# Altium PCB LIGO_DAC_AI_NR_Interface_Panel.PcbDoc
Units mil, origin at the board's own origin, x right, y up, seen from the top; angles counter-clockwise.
Board outline 6300 x 11000 mil, 4 copper layers (Top Layer, Mid-Layer 1, Mid-Layer 2, Bottom Layer), stack 61.8 mil thick; 0 components, 0 nets, 82 pads, 0 vias.
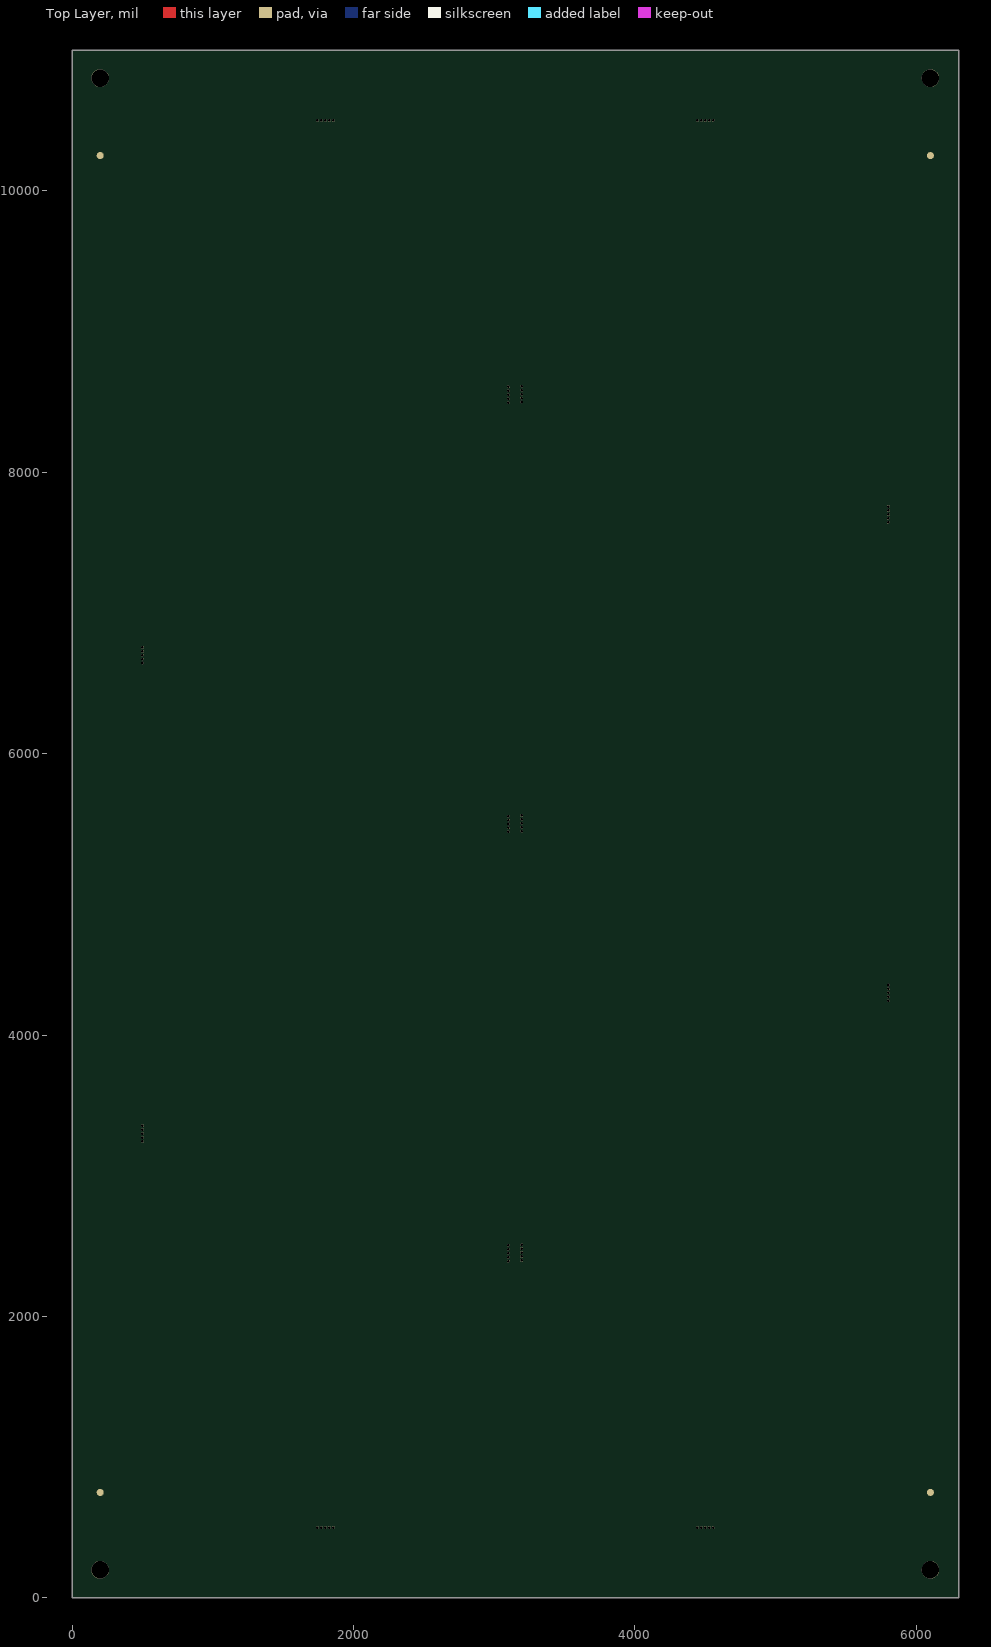
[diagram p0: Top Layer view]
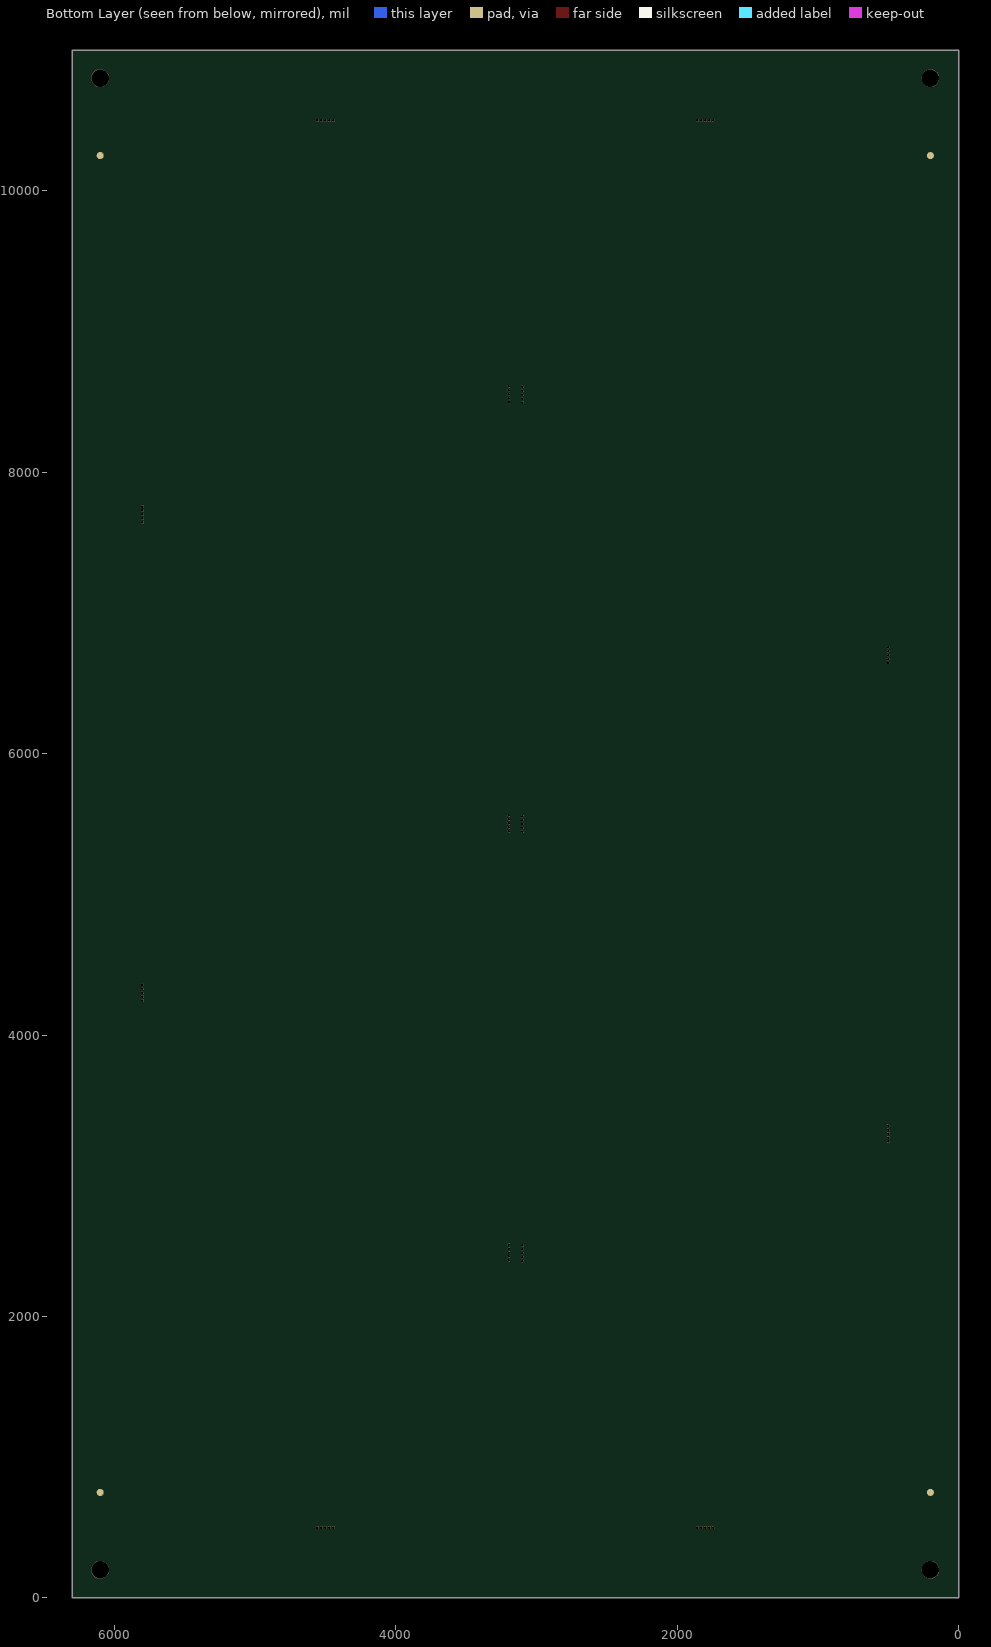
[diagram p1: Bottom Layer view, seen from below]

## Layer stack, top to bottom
Top Solder: solder mask 0.4, Solder Resist, Dk 3.5
Top Layer: signal copper 1.4
Dielectric4: prepreg 8.6, FR-4, Dk 4.8
Mid-Layer 1: signal copper 1.4
Dielectric2: core 39, FR-4, Dk 4.8
Mid-Layer 2: signal copper 1.4
Dielectric3: prepreg 8.6, FR-4, Dk 4.8
Bottom Layer: signal copper 1.4
Bottom Solder: solder mask 0.4, Solder Resist, Dk 3.5

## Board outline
0,0 0,11000 6300,11000 6300,0

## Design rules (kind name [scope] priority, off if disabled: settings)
Clearance [All] p1: gap=10 ignorepadtopadclearanceinfootprint=FALSE
PolygonConnect [All] p1: connectstyle=Relief reliefconductorwidth=10 reliefentries=4 polygonreliefangle="90 Angle" airgapwidth=10
RoutingVias [All] p1: holewidth=28 width=50 viastyle="Through Hole" minholewidth=28 minwidth=50 maxholewidth=28 maxwidth=50
SolderMaskExpansion [All] p1: expansion=4 istentingtop=FALSE
Width [All] p1: maxlimit=10 minlimit=10 preferedwidth=10
30 further rules are at their usual default settings.

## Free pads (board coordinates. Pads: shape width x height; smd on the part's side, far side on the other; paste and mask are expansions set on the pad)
  round 125 hole 125 unplated: 0(200,200) 0(200,10800) 0(6100,200) 0(6100,10800)
  round 50 smd paste-50 mask+50: 0(200,750) 0(200,10250) 0(6100,750) 0(6100,10250)
  round 50 smd far side paste-50 mask+50: 0(200,750) 0(200,10250) 0(6100,750) 0(6100,10250)
  round 18 hole 18 unplated mask+0: 0(500,3244) 0(500,3272) 0(500,3300) 0(500,3328) 0(500,3356) 0(500,6644) 0(500,6672) 0(500,6700) 0(500,6728) 0(500,6756) 0(1744,500) 0(1744,10500) 0(1772,500) 0(1772,10500) 0(1800,500) 0(1800,10500) 0(1828,500) 0(1828,10500) 0(1856,500) 0(1856,10500) 0(3100,2394) 0(3100,2422) 0(3100,2450) 0(3100,2478) 0(3100,2506) 0(3100,5444) 0(3100,5472) 0(3100,5500) 0(3100,5528) 0(3100,5556) 0(3100,8494) 0(3100,8522) 0(3100,8550) 0(3100,8578) 0(3100,8606) 0(3195.62,2398.84) 0(3195.62,2426.84) 0(3195.62,2454.84) 0(3195.62,2482.84) 0(3195.62,2510.84) 0(3195.62,5448.84) 0(3195.62,5476.84) 0(3195.62,5504.84) 0(3195.62,5532.84) 0(3195.62,5560.84) 0(3195.62,8498.84) 0(3195.62,8526.84) 0(3195.62,8554.84) 0(3195.62,8582.84) 0(3195.62,8610.84) 0(4444,500) 0(4444,10500) 0(4472,500) 0(4472,10500) 0(4500,500) 0(4500,10500) 0(4528,500) 0(4528,10500) 0(4556,500) 0(4556,10500) 0(5800,4244) 0(5800,4272) 0(5800,4300) 0(5800,4328) 0(5800,4356) 0(5800,7644) 0(5800,7672) 0(5800,7700) 0(5800,7728) 0(5800,7756)

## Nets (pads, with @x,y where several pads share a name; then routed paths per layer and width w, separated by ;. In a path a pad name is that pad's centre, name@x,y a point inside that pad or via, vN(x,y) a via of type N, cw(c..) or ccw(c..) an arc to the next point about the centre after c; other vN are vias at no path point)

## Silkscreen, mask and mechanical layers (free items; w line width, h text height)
Mechanical 1:
  the board outline again, w25
Mechanical 4:
  lines w100: 450,3200 450,450 1700,450 ; 450,3400 450,3945 490,3945 490,6495 450,6495 450,6600 ; 450,6800 450,6915 490,6915 490,9465 450,9465 450,10550 1700,10550 ; 1900,450 4400,450 ; 1900,10550 4400,10550 ; 3150,450 3150,2350 ; 3150,2550 3150,5400 ; 3150,5600 3150,8450 ; 3150,8650 3150,10550 ; 4600,450 5850,450 5850,1535 5810,1535 5810,4085 5850,4085 5850,4200 ; 4600,10550 5850,10550 5850,7800 ; 5850,4400 5850,4505 5810,4505 5810,7055 5850,7055 5850,7600
Drill Drawing:
  drawing of 663 lines, arcs and shapes, not listed
  text "Layer" at 9327.5,9462.4 h60
  text "Name" at 9737.41,9462.4 h60
  text "Material" at 10667.16,9462.4 h60
  text "Thickness" at 11526.92,9462.4 h60
  text "Constant" at 12176.76,9462.4 h60
  text "Board Layer Stack" at 12746.62,9462.4 h60
  text "Hole Tolerance (-)" at 6600,9437.37 h72 r90
  text "Top Overlay" at 9737.41,9342.4 h60
  text "Top Solder" at 9737.41,9222.4 h60
  text "Solder Resist" at 10667.16,9222.4 h60
  text "0.40mil" at 11526.92,9222.4 h60
  text "3.5" at 12176.76,9222.4 h60
  text "1" at 9327.5,9102.4 h60
  text "Top Layer" at 9737.41,9102.4 h60
  text "1.40mil" at 11526.92,9102.4 h60
  text "Dielectric4" at 9737.41,8982.4 h60
  text "FR-4" at 10667.16,8982.4 h60
  text "8.60mil" at 11526.92,8982.4 h60
  text "4.8" at 12176.76,8982.4 h60
  text "2" at 9327.5,8862.4 h60
  text "Mid-Layer 1" at 9737.41,8862.4 h60
  text "1.40mil" at 11526.92,8862.4 h60
  text "Dielectric2" at 9737.41,8742.4 h60
  text "FR-4" at 10667.16,8742.4 h60
  text "39.00mil" at 11526.92,8742.4 h60
  text "4.8" at 12176.76,8742.4 h60
  text "3" at 9327.5,8622.4 h60
  text "Mid-Layer 2" at 9737.41,8622.4 h60
  text "1.40mil" at 11526.92,8622.4 h60
  text "Dielectric3" at 9737.41,8502.4 h60
  text "FR-4" at 10667.16,8502.4 h60
  text "8.60mil" at 11526.92,8502.4 h60
  text "4.8" at 12176.76,8502.4 h60
  text "4" at 9327.5,8382.4 h60
  text "Bottom Layer" at 9737.41,8382.4 h60
  text "1.40mil" at 11526.92,8382.4 h60
  text "Bottom Solder" at 9737.41,8262.4 h60
  text "Solder Resist" at 10667.16,8262.4 h60
  text "0.40mil" at 11526.92,8262.4 h60
  text "3.5" at 12176.76,8262.4 h60
  text "Bottom Overlay" at 9737.41,8142.4 h60
  text "Hole Tolerance (+)" at 6600,8103.76 h72 r90
  text "Description" at 6600,7250 h72 r90
  text "Template" at 6600,6560.19 h72 r90
  text "v127h71" at 6750,6560.19 h60 r90
  text "c160h80" at 6900,6560.19 h60 r90
  text "(Mixed)" at 7050,6560.19 h60 r90
  text "c318hn318" at 7200,6560.19 h60 r90
  text "c254h158" at 7350,6560.19 h60 r90
  text "(Mixed)" at 7500,6560.19 h60 r90
  text "c455h277" at 7650,6560.19 h60 r90
  text "c635h381" at 7800,6560.19 h60 r90
  text "c476h326" at 7950,6560.19 h60 r90
  text "v102h51" at 8100,6560.19 h60 r90
  text "v64h30" at 8250,6560.19 h60 r90
  text "c46hn46m46" at 8400,6560.19 h60 r90
  text "(Mixed)" at 8550,6560.19 h60 r90
  text "c127h76" at 8700,6560.19 h60 r90
  text "Pad Shape" at 6600,5814.39 h72 r90
  text "Rounded" at 6750,5814.39 h60 r90
  text "Rounded" at 6900,5814.39 h60 r90
  text "(Mixed)" at 7050,5814.39 h60 r90
  text "Rounded" at 7200,5814.39 h60 r90
  text "Rounded" at 7350,5814.39 h60 r90
  text "(Mixed)" at 7500,5814.39 h60 r90
  text "Rounded" at 7650,5814.39 h60 r90
  text "Rounded" at 7800,5814.39 h60 r90
  text "Rounded" at 7950,5814.39 h60 r90
  text "Rounded" at 8100,5814.39 h60 r90
  text "Rounded" at 8250,5814.39 h60 r90
  text "Rounded" at 8400,5814.39 h60 r90
  text "(Mixed)" at 8550,5814.39 h60 r90
  text "Rounded" at 8700,5814.39 h60 r90
  text "Via/Pad" at 6600,5224.54 h72 r90
  text "Via" at 6750,5224.54 h60 r90
  text "Pad" at 6900,5224.54 h60 r90
  text "Pad" at 7050,5224.54 h60 r90
  text "Pad" at 7200,5224.54 h60 r90
  text "Pad" at 7350,5224.54 h60 r90
  text "Pad" at 7500,5224.54 h60 r90
  text "Pad" at 7650,5224.54 h60 r90
  text "Pad" at 7800,5224.54 h60 r90
  text "Pad" at 7950,5224.54 h60 r90
  text "Via" at 8100,5224.54 h60 r90
  text "Via" at 8250,5224.54 h60 r90
  text "Pad" at 8400,5224.54 h60 r90
  text "Pad" at 8550,5224.54 h60 r90
  text "Pad" at 8700,5224.54 h60 r90
  text "Drill Layer Pair" at 6600,3724.99 h72 r90
  text "Top Layer - Bottom Layer" at 6750,3724.99 h60 r90
  text "Top Layer - Bottom Layer" at 6900,3724.99 h60 r90
  text "Top Layer - Bottom Layer" at 7050,3724.99 h60 r90
  text "Top Layer - Bottom Layer" at 7200,3724.99 h60 r90
  text "Top Layer - Bottom Layer" at 7350,3724.99 h60 r90
  text "Top Layer - Bottom Layer" at 7500,3724.99 h60 r90
  text "Top Layer - Bottom Layer" at 7650,3724.99 h60 r90
  text "Top Layer - Bottom Layer" at 7800,3724.99 h60 r90
  text "Top Layer - Bottom Layer" at 7950,3724.99 h60 r90
  text "Top Layer - Bottom Layer" at 8100,3724.99 h60 r90
  text "Top Layer - Bottom Layer" at 8250,3724.99 h60 r90
  text "Top Layer - Bottom Layer" at 8400,3724.99 h60 r90
  text "Top Layer - Bottom Layer" at 8550,3724.99 h60 r90
  text "Top Layer - Bottom Layer" at 8700,3724.99 h60 r90
  text "Hole Type" at 6600,2991.19 h72 r90
  text "Round" at 6750,2991.19 h60 r90
  text "Round" at 6900,2991.19 h60 r90
  text "Round" at 7050,2991.19 h60 r90
  text "Round" at 7200,2991.19 h60 r90
  text "Round" at 7350,2991.19 h60 r90
  text "Round" at 7500,2991.19 h60 r90
  text "Round" at 7650,2991.19 h60 r90
  text "Round" at 7800,2991.19 h60 r90
  text "Round" at 7950,2991.19 h60 r90
  text "Round" at 8100,2991.19 h60 r90
  text "Round" at 8250,2991.19 h60 r90
  text "Round" at 8400,2991.19 h60 r90
  text "Round" at 8550,2991.19 h60 r90
  text "Round" at 8700,2991.19 h60 r90
  text "Plated" at 6600,2485.31 h72 r90
  text "PTH" at 6750,2485.31 h60 r90
  text "PTH" at 6900,2485.31 h60 r90
  text "PTH" at 7050,2485.31 h60 r90
  text "NPTH" at 7200,2485.31 h60 r90
  text "PTH" at 7350,2485.31 h60 r90
  text "PTH" at 7500,2485.31 h60 r90
  text "PTH" at 7650,2485.31 h60 r90
  text "PTH" at 7800,2485.31 h60 r90
  text "PTH" at 7950,2485.31 h60 r90
  text "PTH" at 8100,2485.31 h60 r90
  text "PTH" at 8250,2485.31 h60 r90
  text "NPTH" at 8400,2485.31 h60 r90
  text "PTH" at 8550,2485.31 h60 r90
  text "PTH" at 8700,2485.31 h60 r90
  text "Hole Size" at 6600,1335.65 h72 r90
  text "28.00mil (0.711mm)" at 6750,1335.65 h60 r90
  text "31.50mil (0.800mm)" at 6900,1335.65 h60 r90
  text "40.16mil (1.020mm)" at 7050,1335.65 h60 r90
  text "125.00mil (3.175mm)" at 7200,1335.65 h60 r90
  text "62.21mil (1.580mm)" at 7350,1335.65 h60 r90
  text "68.90mil (1.750mm)" at 7500,1335.65 h60 r90
  text "109.06mil (2.770mm)" at 7650,1335.65 h60 r90
  text "150.00mil (3.810mm)" at 7800,1335.65 h60 r90
  text "128.35mil (3.260mm)" at 7950,1335.65 h60 r90
  text "20.00mil (0.508mm)" at 8100,1335.65 h60 r90
  text "12.00mil (0.305mm)" at 8250,1335.65 h60 r90
  text "18.00mil (0.457mm)" at 8400,1335.65 h60 r90
  text "42.91mil (1.090mm)" at 8550,1335.65 h60 r90
  text "30.00mil (0.762mm)" at 8700,1335.65 h60 r90
  text "Count" at 6600,735.81 h72 r90
  text "2" at 6750,735.81 h60 r90
  text "4" at 6900,735.81 h60 r90
  text "4" at 7050,735.81 h60 r90
  text "4" at 7200,735.81 h60 r90
  text "6" at 7350,735.81 h60 r90
  text "8" at 7500,735.81 h60 r90
  text "8" at 7650,735.81 h60 r90
  text "8" at 7800,735.81 h60 r90
  text "16" at 7950,735.81 h60 r90
  text "22" at 8100,735.81 h60 r90
  text "60" at 8250,735.81 h60 r90
  text "70" at 8400,735.81 h60 r90
  text "72" at 8550,735.81 h60 r90
  text "272" at 8700,735.81 h60 r90
  text "556 Total" at 8850,735.81 h60 r90
  text "Symbol" at 6600,229.93 h72 r90

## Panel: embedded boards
"LIGO_DAC_AI_NR_Interface.PcbDoc" at 500,500, 1 rows x 1 columns, spacing 2500 x 1500, rotation 0
"LIGO_DAC_AI_NR_Interface.PcbDoc" at 5800,10500, 1 rows x 1 columns, spacing 2500 x 1500, rotation 180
